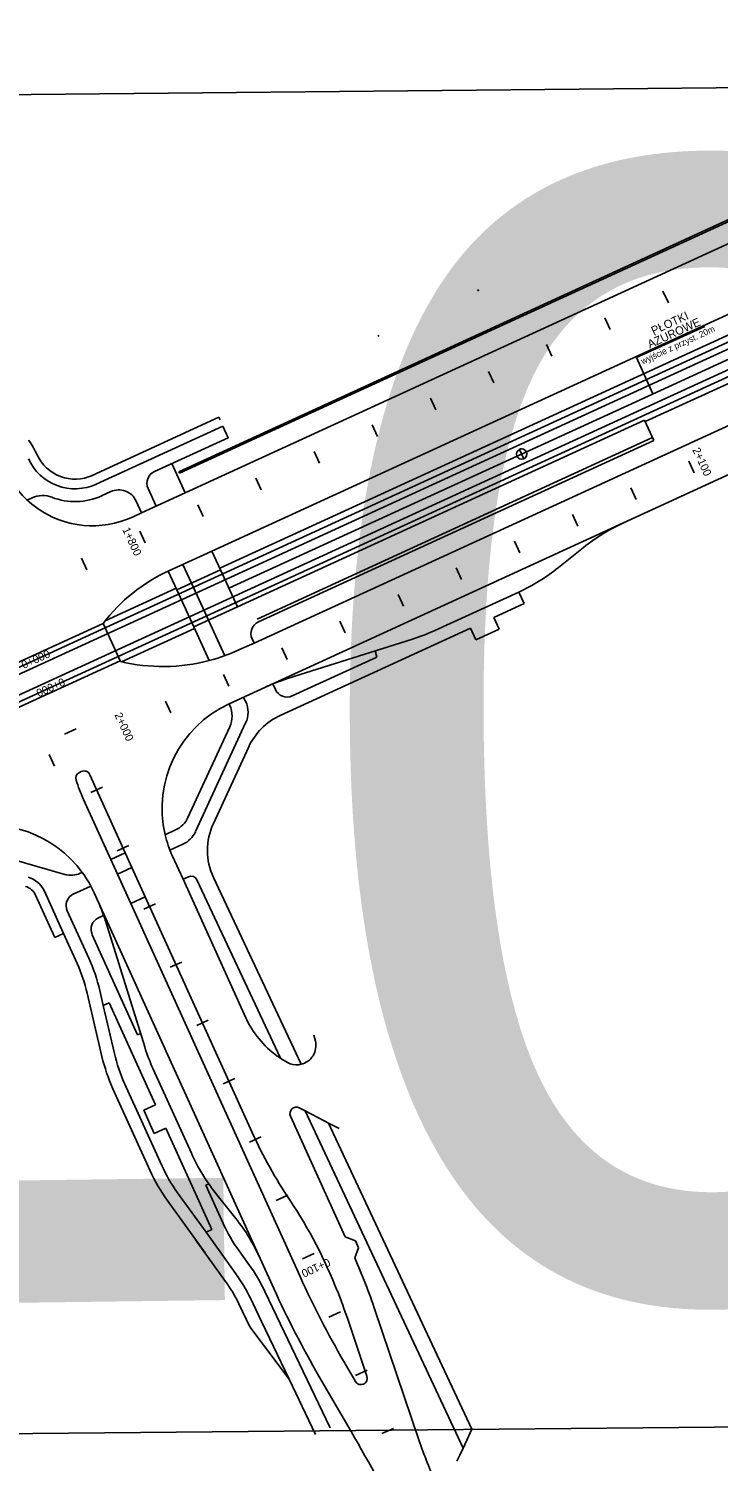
# Model space of a CAD drawing. Extents: x 6503541 to 6503743, y 5888004 to 5888145.
# Drawn here: x 6503636.59 to 6503639.18, y 5888067.22 to 5888072.59 of the extents above; entities that cross this region are included whole.
import ezdxf

# ---------------------------------------------------------------- set-up
doc = ezdxf.new("R2010")
doc.units = 0
doc.layers.add('12', color=7, linetype='Continuous')
doc.layers.add('tabela', color=7, linetype='Continuous')

msp = doc.modelspace()

# ---------------------------------------------------------------- linework, layer by layer
at = {"layer": '12'}
for p, q in [((6503624.2939, 5888064.5761), (6503641.7343, 5888072.5724)), ((6503637.3116, 5888070.5709), (6503641.7244, 5888072.5939)), ((6503624.3039, 5888064.5543), (6503641.7443, 5888072.5505)), ((6503640.659, 5888072.5377), (6503637.1578, 5888070.9324)), ((6503640.6615, 5888072.5322), (6503637.1603, 5888070.9269)), ((6503624.3329, 5888064.491), (6503641.7733, 5888072.4873)), ((6503624.3429, 5888064.4692), (6503641.7833, 5888072.4655)), ((6503640.6941, 5888072.4638), (6503637.182, 5888070.8535)), ((6503638.9077, 5888071.1206), (6503641.7933, 5888072.4436)), ((6503641.0219, 5888071.7481), (6503638.8257, 5888070.7411)), ((6503639.4175, 5888071.6144), (6503637.282, 5888070.6353)), ((6503638.2816, 5888071.6098), (6503638.2791, 5888071.6153)), ((6503640.2442, 5888071.5763), (6503637.4401, 5888070.2906)), ((6503637.9055, 5888071.4452), (6503637.9079, 5888071.4397)), ((6503639.1307, 5888071.477), (6503638.8752, 5888071.3608)), ((6503638.8717, 5888071.1952), (6503639.3081, 5888071.3953)), ((6503638.8752, 5888071.3608), (6503638.9361, 5888071.2247)), ((6503637.346, 5888070.4957), (6503638.8717, 5888071.1952)), ((6503637.3087, 5888071.1368), (6503636.8336, 5888070.919)), ((6503637.3128, 5888071.1278), (6503637.3087, 5888071.1368)), ((6503638.9052, 5888071.1261), (6503637.3781, 5888070.4259)), ((6503638.9052, 5888071.1261), (6503638.9402, 5888071.0497)), ((6503637.3237, 5888071.1041), (6503636.8486, 5888070.8862)), ((6503637.3237, 5888071.1041), (6503637.3437, 5888071.0604)), ((6503637.3437, 5888071.0604), (6503637.0662, 5888070.9332)), ((6503637.3446, 5888071.0585), (6503637.3437, 5888071.0604)), ((6503638.9352, 5888071.0606), (6503637.4517, 5888070.3804)), ((6503638.9402, 5888071.0497), (6503637.4567, 5888070.3695)), ((6503637.1317, 5888070.9632), (6503637.182, 5888070.8535)), ((6503637.1603, 5888070.9269), (6503637.1578, 5888070.9324)), ((6503636.9026, 5888070.8582), (6503636.8686, 5888070.8426)), ((6503637.182, 5888070.8535), (6503637.0184, 5888070.7785)), ((6503637.0426, 5888070.8696), (6503637.0729, 5888070.8035)), ((6503636.6079, 5888070.8347), (6503636.5894, 5888070.8263)), ((6503636.9981, 5888070.8228), (6503637.0184, 5888070.7785)), ((6503637.0184, 5888070.7785), (6503636.9843, 5888070.7629)), ((6503638.8257, 5888070.7411), (6503637.4827, 5888070.1254)), ((6503637.282, 5888070.6353), (6503637.1203, 5888070.5612)), ((6503637.282, 5888070.6353), (6503637.1203, 5888070.5612)), ((6503637.282, 5888070.6353), (6503637.314, 5888070.5655)), ((6503638.5826, 5888070.5741), (6503638.676, 5888070.6488)), ((6503637.173, 5888070.5853), (6503637.205, 5888070.5155)), ((6503637.1184, 5888070.5603), (6503637.1504, 5888070.4905)), ((6503637.314, 5888070.5655), (6503637.1504, 5888070.4905)), ((6503637.3781, 5888070.4259), (6503637.314, 5888070.5655)), ((6503637.1479, 5888070.496), (6503636.8821, 5888070.3741)), ((6503636.8821, 5888070.3741), (6503637.1479, 5888070.4959)), ((6503637.1504, 5888070.4905), (6503637.2144, 5888070.3509)), ((6503637.205, 5888070.5155), (6503637.269, 5888070.3759)), ((6503638.1178, 5888070.3373), (6503638.4328, 5888070.4818)), ((6503638.4328, 5888070.4818), (6503638.4528, 5888070.4381)), ((6503637.3781, 5888070.4259), (6503637.2144, 5888070.3509)), ((6503638.339, 5888070.3859), (6503638.4528, 5888070.4381)), ((6503637.33, 5888070.2428), (6503637.269, 5888070.3759)), ((6503638.359, 5888070.3423), (6503638.339, 5888070.3859)), ((6503636.8742, 5888070.3638), (6503636.412, 5888070.1519)), ((6503636.8742, 5888070.3638), (6503636.412, 5888070.1519)), ((6503636.8742, 5888070.3638), (6503636.939, 5888070.2211)), ((6503636.8742, 5888070.3638), (6503636.939, 5888070.2211)), ((6503636.9435, 5888070.2201), (6503637.2169, 5888070.3454)), ((6503637.2144, 5888070.3509), (6503637.2722, 5888070.2249)), ((6503637.538, 5888070.0187), (6503638.2517, 5888070.3459)), ((6503638.2717, 5888070.3023), (6503638.2517, 5888070.3459)), ((6503638.359, 5888070.3423), (6503638.2717, 5888070.3023)), ((6503637.4401, 5888070.2906), (6503637.3832, 5888070.2646)), ((6503637.4401, 5888070.2906), (6503637.3832, 5888070.2646)), ((6503637.4331, 5888070.3059), (6503637.4401, 5888070.2906)), ((6503637.5662, 5888070.1575), (6503638.0343, 5888070.3052)), ((6503637.9012, 5888070.238), (6503637.894, 5888070.2609)), ((6503636.9377, 5888070.224), (6503636.4755, 5888070.0121)), ((6503636.9377, 5888070.224), (6503636.4755, 5888070.0121)), ((6503637.5837, 5888070.0925), (6503637.9012, 5888070.238)), ((6503637.4827, 5888070.1254), (6503637.3465, 5888070.0629)), ((6503637.5201, 5888070.1161), (6503637.5104, 5888070.1373)), ((6503637.3465, 5888070.0629), (6503637.3493, 5888070.0567)), ((6503637.4087, 5888070.071), (6503637.401, 5888070.0879)), ((6503637.4086, 5888069.9908), (6503637.2205, 5888069.5833)), ((6503637.3492, 5888069.9765), (6503637.1923, 5888069.6367)), ((6503637.4201, 5888069.9011), (6503637.2875, 5888069.6138)), ((6503636.7923, 5888069.8088), (6503636.7855, 5888069.8057)), ((6503636.9572, 5888069.504), (6503636.8242, 5888069.7969)), ((6503636.9026, 5888069.4792), (6503636.8004, 5888069.7042)), ((6503637.1455, 5888069.5898), (6503637.1068, 5888069.5719)), ((6503636.4343, 5888069.5078), (6503636.7306, 5888069.423)), ((6503637.1731, 5888069.5361), (6503637.1247, 5888069.5141)), ((6503636.9026, 5888069.4792), (6503636.9572, 5888069.504)), ((6503636.9776, 5888069.3139), (6503636.9026, 5888069.4792)), ((6503637.0322, 5888069.3388), (6503636.9572, 5888069.504)), ((6503637.1737, 5888069.4046), (6503637.134, 5888069.4919)), ((6503636.7884, 5888069.4273), (6503636.7959, 5888069.4307)), ((6503636.9274, 5888069.4245), (6503636.982, 5888069.4493)), ((6503637.1944, 5888069.414), (6503637.1737, 5888069.4046)), ((6503637.4093, 5888068.8857), (6503637.1737, 5888069.4046)), ((6503637.5395, 5888068.7336), (6503637.2261, 5888069.4023)), ((6503637.6163, 5888068.7111), (6503637.2881, 5888069.4114)), ((6503636.6929, 5888069.1863), (6503636.6208, 5888069.3451)), ((6503636.7257, 5888069.2012), (6503636.6536, 5888069.36)), ((6503636.7616, 5888069.3492), (6503636.8282, 5888069.3795)), ((6503636.8522, 5888069.3288), (6503636.8408, 5888069.3541)), ((6503637.4631, 5888067.9835), (6503636.8522, 5888069.3288)), ((6503636.9776, 5888069.3139), (6503637.0322, 5888069.3388)), ((6503637.6127, 5888067.9152), (6503636.9776, 5888069.3139)), ((6503637.4334, 5888068.4554), (6503637.0322, 5888069.3388)), ((6503636.8202, 5888069.1091), (6503636.7396, 5888069.2866)), ((6503636.8568, 5888069.2607), (6503636.8761, 5888069.2694)), ((6503636.8841, 5888069.2452), (6503637.03, 5888068.7765)), ((6503636.8841, 5888069.2452), (6503637.03, 5888068.7765)), ((6503636.6929, 5888069.1863), (6503636.7257, 5888069.2012)), ((6503636.7765, 5888069.0893), (6503636.7257, 5888069.2012)), ((6503637.0036, 5888068.8213), (6503636.833, 5888069.1971)), ((6503636.8145, 5888068.9773), (6503636.8698, 5888068.7401)), ((6503636.8613, 5888068.9882), (6503636.8745, 5888068.9315)), ((6503636.8963, 5888068.9414), (6503636.8745, 5888068.9315)), ((6503636.8745, 5888068.9315), (6503636.9165, 5888068.751)), ((6503636.8963, 5888068.9414), (6503637.07, 5888068.559)), ((6503637.0145, 5888068.8263), (6503637.0036, 5888068.8213)), ((6503637.6701, 5888068.7981), (6503637.6649, 5888068.8198)), ((6503637.5395, 5888068.7336), (6503637.5395, 5888068.7336)), ((6503637.0619, 5888068.6929), (6503637.2052, 5888068.3774)), ((6503637.0503, 5888068.3122), (6503636.9109, 5888068.6192)), ((6503637.094, 5888068.332), (6503636.9546, 5888068.6391)), ((6503637.0263, 5888068.5392), (6503637.07, 5888068.559)), ((6503637.6098, 5888068.5478), (6503637.6172, 5888068.544)), ((6503637.6172, 5888068.544), (6503637.632, 5888068.5363)), ((6503637.066, 5888068.4518), (6503637.0263, 5888068.5392)), ((6503637.7824, 5888068.064), (6503637.5769, 5888068.5165)), ((6503637.632, 5888068.5363), (6503637.7034, 5888068.4993)), ((6503638.2244, 5888067.2724), (6503637.632, 5888068.5363)), ((6503637.7034, 5888068.4993), (6503637.7193, 5888068.491)), ((6503637.7193, 5888068.491), (6503637.7593, 5888068.4703)), ((6503638.2576, 5888067.3429), (6503637.7195, 5888068.4909)), ((6503637.066, 5888068.4518), (6503637.1097, 5888068.4716)), ((6503637.2824, 5888068.0914), (6503637.1097, 5888068.4716)), ((6503637.2601, 5888068.0812), (6503637.1532, 5888068.2297)), ((6503637.2703, 5888068.2631), (6503637.2594, 5888068.2581)), ((6503637.3248, 5888068.1139), (6503637.2594, 5888068.2581)), ((6503637.2969, 5888068.2273), (6503637.3713, 5888068.1336)), ((6503637.2565, 5888068.004), (6503637.1143, 5888068.2017)), ((6503637.2601, 5888068.0812), (6503637.2824, 5888068.0914)), ((6503637.3722, 5888067.9253), (6503637.2601, 5888068.0812)), ((6503637.7824, 5888068.064), (6503637.8205, 5888068.0497)), ((6503637.3333, 5888067.8973), (6503637.2211, 5888068.0532)), ((6503637.3841, 5888068.0116), (6503637.4209, 5888067.9604)), ((6503637.818, 5888067.9851), (6503637.8324, 5888068.0235)), ((6503637.8205, 5888068.0497), (6503637.8324, 5888068.0235)), ((6503637.5144, 5888067.8706), (6503637.4631, 5888067.9835)), ((6503637.7251, 5888067.3488), (6503637.4805, 5888067.8599)), ((6503637.4245, 5888067.7267), (6503637.3831, 5888067.8132)), ((6503637.4678, 5888067.7474), (6503637.4264, 5888067.834)), ((6503637.8937, 5888067.79), (6503638.0587, 5888067.3031)), ((6503637.5714, 5888067.5309), (6503637.4678, 5888067.7474)), ((6503637.7914, 5888067.7554), (6503637.8638, 5888067.5418)), ((6503637.5714, 5888067.5309), (6503637.4245, 5888067.7267)), ((6503637.7771, 5888067.5965), (6503637.8203, 5888067.5221)), ((6503637.671, 5888067.3229), (6503637.5714, 5888067.5309)), ((6503637.6837, 5888067.5422), (6503637.8043, 5888067.3344)), ((6503638.2244, 5888067.2724), (6503638.245, 5888067.3161)), ((6503638.245, 5888067.3161), (6503638.2576, 5888067.343)), ((6503638.2116, 5888067.2451), (6503638.2244, 5888067.2724)), ((6503638.201, 5888067.2226), (6503638.2116, 5888067.2451))]:
    msp.add_line(p, q, dxfattribs=at)
for points in [[(6503638.9941, 5888071.5655), (6503638.974, 5888071.6091)], [(6503638.7759, 5888071.4655), (6503638.7559, 5888071.5091)], [(6503638.5577, 5888071.3654), (6503638.5377, 5888071.4091)], [(6503638.3396, 5888071.2654), (6503638.3196, 5888071.309)], [(6503638.1214, 5888071.1654), (6503638.1014, 5888071.209)], [(6503637.9032, 5888071.0654), (6503637.8832, 5888071.109)], [(6503638.4358, 5888071.0164), (6503638.4518, 5888070.9815)], [(6503637.6851, 5888070.9653), (6503637.6651, 5888071.009)], [(6503639.0714, 5888070.9726), (6503639.0914, 5888070.9289)], [(6503637.4669, 5888070.8653), (6503637.4469, 5888070.9089)], [(6503638.8732, 5888070.8289), (6503638.8532, 5888070.8725)], [(6503637.2488, 5888070.7653), (6503637.2287, 5888070.8089)], [(6503638.6551, 5888070.7289), (6503638.6351, 5888070.7725)], [(6503637.0123, 5888070.7097), (6503637.0323, 5888070.666)], [(6503638.4369, 5888070.6289), (6503638.4169, 5888070.6725)], [(6503636.8124, 5888070.5652), (6503636.7924, 5888070.6089)], [(6503638.2187, 5888070.5288), (6503638.1987, 5888070.5725)], [(6503638.0006, 5888070.4288), (6503637.9806, 5888070.4724)], [(6503637.7824, 5888070.3288), (6503637.7624, 5888070.3724)], [(6503637.5642, 5888070.2288), (6503637.5442, 5888070.2724)], [(6503637.3461, 5888070.1287), (6503637.3261, 5888070.1724)], [(6503637.1279, 5888070.0287), (6503637.1079, 5888070.0723)], [(6503636.7289, 5888069.9488), (6503636.7726, 5888069.9686)], [(6503636.6916, 5888069.8286), (6503636.6716, 5888069.8723)], [(6503636.8281, 5888069.7303), (6503636.8718, 5888069.7501)], [(6503636.9273, 5888069.5117), (6503636.971, 5888069.5316)], [(6503637.0266, 5888069.2932), (6503637.0703, 5888069.3131)], [(6503637.1258, 5888069.0747), (6503637.1695, 5888069.0945)], [(6503637.225, 5888068.8562), (6503637.2687, 5888068.876)], [(6503637.3242, 5888068.6376), (6503637.3679, 5888068.6575)], [(6503637.4235, 5888068.4191), (6503637.4672, 5888068.439)], [(6503637.5227, 5888068.2006), (6503637.5664, 5888068.2204)], [(6503637.6656, 5888068.0019), (6503637.6219, 5888067.9821)], [(6503637.7212, 5888067.7635), (6503637.7649, 5888067.7834)], [(6503637.8204, 5888067.545), (6503637.8641, 5888067.5648)], [(6503637.9196, 5888067.3265), (6503637.9633, 5888067.3463)]]:
    msp.add_lwpolyline(points, dxfattribs=at)
msp.add_circle((6503638.4438, 5888070.999), 0.0192, dxfattribs=at)
for centre, radius, start, end in [((6503636.3317, 5888070.8619), 0.324, 24.4219, 35.7318), ((6503638.4438, 5888070.999), 0.0192, 350.1838, 114.6311), ((6503636.7686, 5888071.0608), 0.192, 204.4219, 294.6311), ((6503636.7686, 5888071.0608), 0.156, 204.4219, 294.6311), ((6503638.4438, 5888070.999), 0.0192, 294.6311, 350.1838), ((6503636.8343, 5888071.0901), 0.36, 204.4219, 234.4219), ((6503637.0862, 5888070.8896), 0.048, 114.6311, 204.6311), ((6503636.9326, 5888070.7928), 0.072, 24.6311, 114.6311), ((6503636.6476, 5888070.7473), 0.096, 68.894, 114.4219), ((6503636.8343, 5888071.0901), 0.36, 234.4219, 294.6304), ((6503636.7686, 5888071.0608), 0.24, 248.894, 294.6311), ((6503639.1258, 5888070.0866), 0.72, 114.6311, 128.6673), ((6503637.3904, 5888069.9722), 0.648, 114.6311, 142.8095), ((6503637.3904, 5888069.9722), 0.648, 114.6311, 114.8178), ((6503638.1328, 5888071.1362), 0.72, 294.6311, 308.6673), ((6503637.3904, 5888069.9722), 0.648, 141.6646, 142.8095), ((6503637.4767, 5888070.3259), 0.048, 114.6311, 204.6311), ((6503637.8177, 5888070.9918), 0.72, 287.506, 294.6311), ((6503637.0982, 5888070.8863), 0.684, 284.7413, 294.6311), ((6503637.0982, 5888070.8863), 0.684, 284.7413, 294.6309), ((6503637.0982, 5888070.8863), 0.684, 256.5434, 284.7413), ((6503637.0982, 5888070.8863), 0.684, 256.5434, 256.9301), ((6503637.7828, 5888069.4709), 0.72, 107.506, 112.2343), ((6503637.7828, 5888069.4709), 0.72, 112.2343, 114.6311), ((6503637.5637, 5888070.1361), 0.048, 204.6311, 294.6311), ((6503637.5273, 5888069.6706), 0.432, 114.7508, 193.208), ((6503637.262, 5888070.0167), 0.096, 335.2226, 24.6311), ((6503637.3215, 5888070.031), 0.096, 335.2226, 24.6311), ((6503637.638, 5888069.8005), 0.24, 114.6311, 155.2226), ((6503636.7955, 5888069.7839), 0.024, 114.6311, 197.5613), ((6503637.3904, 5888069.9722), 0.648, 197.5613, 204.4219), ((6503636.8023, 5888069.787), 0.024, 24.4219, 114.6311), ((6503637.1052, 5888069.6769), 0.096, 294.8402, 335.2226), ((6503637.5054, 5888069.5132), 0.24, 155.2226, 205.1123), ((6503636.4474, 5888069.1755), 0.432, 36.2231, 104.4437), ((6503637.5273, 5888069.6706), 0.432, 193.208, 204.4219), ((6503637.1334, 5888069.6235), 0.096, 294.4219, 335.2226), ((6503636.5662, 5888069.3203), 0.096, 24.4219, 74.0395), ((6503636.7537, 5888069.5038), 0.084, 254.0395, 294.4219), ((6503636.4474, 5888069.1755), 0.432, 24.4219, 36.2231), ((6503637.2044, 5888069.3921), 0.024, 25.1123, 114.4219), ((6503636.5662, 5888069.3203), 0.06, 24.4219, 74.0395), ((6503636.7833, 5888069.3064), 0.048, 114.4219, 204.4219), ((6503636.1966, 5888069.0311), 0.72, 19.3308, 24.4219), ((6503636.8767, 5888069.217), 0.048, 114.4219, 204.4219), ((6503636.1966, 5888069.0311), 0.72, 17.2969, 19.3308), ((6503636.2302, 5888068.8412), 0.6, 13.112, 24.4219), ((6503636.2302, 5888068.8412), 0.648, 13.1125, 24.4219), ((6503637.7371, 5888069.0346), 0.36, 204.4219, 234.3483), ((6503637.7175, 5888068.9906), 0.72, 197.2969, 204.4219), ((6503637.7175, 5888068.9906), 0.72, 197.2969, 204.4219), ((6503637.6001, 5888068.7812), 0.072, 283.0305, 13.5639), ((6503637.5009, 5888068.8871), 0.648, 193.112, 204.4219), ((6503637.5009, 5888068.8871), 0.6, 193.112, 204.4219), ((6503637.7371, 5888069.0346), 0.36, 234.3483, 236.7177), ((6503637.7371, 5888069.0346), 0.36, 236.7177, 241.6046), ((6503637.6001, 5888068.7812), 0.072, 241.6046, 276.1727), ((6503637.6001, 5888068.7812), 0.072, 276.1727, 283.0305), ((6503637.5988, 5888068.5265), 0.024, 62.603, 204.4219), ((6503639.0723, 5888069.1996), 1.8, 204.4219, 213.7274), ((6503637.6403, 5888068.5801), 0.6, 204.4219, 215.7318), ((6503637.8607, 5888068.6751), 0.72, 204.4221, 218.4581), ((6503637.6403, 5888068.5801), 0.648, 204.4219, 215.7318), ((6503636.0782, 5888067.2007), 1.8, 21.5336, 33.7274), ((6503637.8711, 5888068.362), 0.6, 204.4219, 215.7318), ((6503636.8075, 5888067.6858), 0.72, 24.4219, 38.4581), ((6503636.8852, 5888067.5749), 0.66, 25.5757, 35.7318), ((6503635.6206, 5888067.0201), 2.4, 18.7113, 23.7077), ((6503636.8852, 5888067.5749), 0.552, 25.5757, 35.7318), ((6503636.8852, 5888067.5749), 0.6, 25.5757, 35.7318), ((6503640.8906, 5888069.4037), 3.6, 204.4219, 210.1325), ((6503640.8906, 5888069.4037), 3.708, 204.4216, 210.1325), ((6503635.6206, 5888067.0201), 2.292, 18.7113, 21.5336), ((6503637.841, 5888067.5341), 0.024, 210.1325, 18.7113), ((6503630.5394, 5888063.1176), 8.4, 24.42189, 30.13249), ((6503639.7635, 5888067.8805), 1.8, 198.7113, 204.4756)]:
    msp.add_arc(centre, radius, start, end, dxfattribs=at)
at = {"layer": 'tabela'}
for p, q in [((6503634.7976, 5888072.3306), (6503642.0331, 5888072.3982)), ((6503642.0799, 5888067.3781), (6503634.8445, 5888067.3105))]:
    msp.add_line(p, q, dxfattribs=at)

# ---------------------------------------------------------------- texts
at = {"layer": '12'}
for s, height, rotation, p in [('10', 4.22297, 0.7393, (6503634.4661, 5888067.7901)), ('AŻUROWE', 0.0311, 24.5449, (6503638.9246, 5888071.3946)), ('PŁOTKI', 0.0311, 24.5449, (6503638.9386, 5888071.4452)), ('wyjście z przyst. 20m', 0.023802, 24.5449, (6503638.898, 5888071.335)), ('2+100', 0.03, 294.6311, (6503639.0834, 5888071.0153)), ('1+800', 0.03, 294.6311, (6503636.9455, 5888070.7163)), ('0+000', 0.03, 24.4219, (6503636.5763, 5888070.1928)), ('0+000', 0.03, 204.4219, (6503636.7224, 5888070.1608)), ('2+000', 0.03, 294.6311, (6503636.9159, 5888070.0215)), ('0+100', 0.03, 204.4219, (6503637.7175, 5888067.9847))]:
    msp.add_text(s, height=height, rotation=rotation, dxfattribs=at).set_placement(p)

doc.saveas('drawing.dxf')
